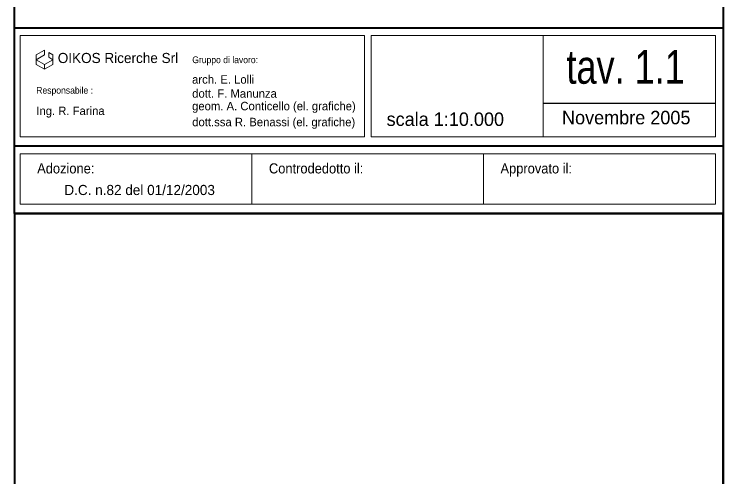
# Model space of a CAD drawing. Extents: x 645880 to 658994, y 884400 to 894744.
# Drawn here: x 647922 to 650059, y 890994 to 892363 of the extents above; entities that cross this region are included whole.
import ezdxf
from ezdxf.enums import TextEntityAlignment as Align

# ---------------------------------------------------------------- set-up
doc = ezdxf.new("R2010")
doc.units = 0
doc.header["$LTSCALE"] = 10
doc.layers.add('62', color=7, linetype='Continuous', lineweight=35)

msp = doc.modelspace()

# ---------------------------------------------------------------- linework, layer by layer
at = {"layer": '62', "lineweight": 40}
for p, q in [((647922.35, 892323.81), (650022.35, 892323.81)), ((647922.35, 891973.81), (650022.35, 891973.81)), ((647922.35, 891773.81), (650022.35, 891773.81))]:
    msp.add_line(p, q, dxfattribs=at)
at = {"layer": '62', "lineweight": 13}
for p, q in [((647939.35, 892300.81), (647939.35, 892000.81)), ((647939.35, 892300.81), (648959.35, 892300.81)), ((648959.35, 892300.81), (648959.35, 892000.81)), ((648979.35, 892300.81), (648979.35, 892000.81)), ((648979.35, 892300.81), (649999.35, 892300.81)), ((649489.35, 892300.81), (649489.35, 892000.81)), ((649999.35, 892300.81), (649999.35, 892000.81)), ((647939.35, 892000.81), (648959.35, 892000.81)), ((648979.35, 892000.81), (649999.35, 892000.81)), ((647939.35, 891950.81), (647939.35, 891800.81)), ((647939.35, 891950.81), (649999.35, 891950.81)), ((648626.01, 891950.81), (648626.01, 891800.81)), ((649312.67, 891950.81), (649312.67, 891800.81)), ((649999.35, 891950.81), (649999.35, 891800.81)), ((647939.35, 891800.81), (649999.35, 891800.81)), ((647922.35, 891773.81), (647922.35, 891113.81))]:
    msp.add_line(p, q, dxfattribs=at)
at = {"layer": '62', "lineweight": 25}
msp.add_line((649489.35, 892100.81), (649999.35, 892100.81), dxfattribs=at)
at = {"layer": '62', "lineweight": 40}
for points in [[(650022.35, 894743.81), (650022.35, 891773.81), (647922.35, 891773.81), (647922.35, 894743.81)], [(650022.35, 889003.81), (658994.16, 889003.81), (658994.16, 894743.81), (650022.35, 894743.81)], [(650022.35, 889003.81), (658994.16, 889003.81), (658994.16, 894743.81), (650022.35, 894743.81)], [(647922.35, 889003.81), (650022.35, 889003.81), (650022.35, 891773.81), (647922.35, 891773.81)]]:
    msp.add_lwpolyline(points, close=True, dxfattribs=at)
at = {"layer": '62', "lineweight": 13}
for points in [[(648011.9, 892257.8), (647987.15, 892243.57), (647987.15, 892229.28), (648011.9, 892243.57)], [(648036.65, 892243.57), (648024.28, 892250.69), (648024.28, 892236.43), (648036.65, 892229.28)], [(648011.9, 892214.99), (647987.15, 892229.28), (647987.15, 892214.99), (648011.9, 892200.76)], [(648036.65, 892229.28), (648011.9, 892214.99), (648011.9, 892200.76), (648036.65, 892214.99)]]:
    msp.add_lwpolyline(points, close=True, dxfattribs=at)

# ---------------------------------------------------------------- texts
at = {"layer": '62'}
for s, height, p in [('OIKOS Ricerche Srl', 30, (648050.8, 892219.33)), ('arch. E. Lolli', 25, (648448.8, 892158.27)), ('dott. F. Manunza', 25, (648449.15, 892116.67)), ('Ing. R. Farina', 25, (647987.15, 892065.29)), ('geom. A. Conticello (el. grafiche)', 25, (648448.73, 892079.37)), ('scala 1:10.000     ', 40, (649025.18, 892032.96)), ('dott.ssa R. Benassi (el. grafiche)', 25, (648449.19, 892032.07)), ('D.C. n.82 del 01/12/2003', 30, (648070.32, 891828.28))]:
    msp.add_text(s, height=height, dxfattribs=at).set_placement(p)
for s, height, width, p in [('Gruppo di lavoro:', 20, 0.95, (648449.25, 892218.97)), ('tav. 1.1', 100, 0.8, (649557.99, 892158.04)), ('Responsabile :', 20, 0.95, (647987.08, 892128.51)), ('Adozione:', 30, 0.95, (647989.79, 891892.26)), ('Controdedotto il:', 30, 0.95, (648676.54, 891892.26)), ('Approvato il:', 30, 0.95, (649362.7, 891892.26))]:
    msp.add_text(s, height=height, dxfattribs=dict(at, width=width)).set_placement(p)
msp.add_text('Novembre 2005', height=40, dxfattribs=at).set_placement((649735.23, 892037.8), align=Align.CENTER)

doc.saveas('drawing.dxf')
